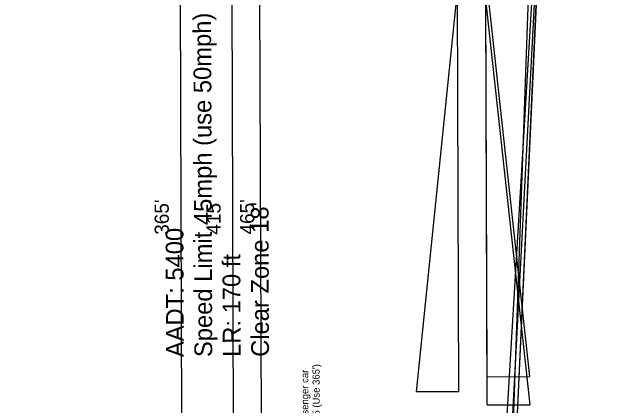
# Model space of a CAD drawing. Extents: x 17465868 to 18455672, y 7253752 to 7478845.
# Drawn here: x 18454911.4 to 18455165.1, y 7478499.2 to 7478665.7 of the extents above; entities that cross this region are included whole.
import ezdxf

# ---------------------------------------------------------------- set-up
doc = ezdxf.new("R2010")
doc.units = 0
for name, color, linetype in [('Clinton 225 CL Girders', 7, 'Continuous'), ('Clinton 225 CL Truss', 7, 'Continuous'), ('Clinton 225 Handrail', 7, 'Continuous'), ('Clinton 225 Metal Rail', 7, 'Continuous'), ('Clinton 225 MISC', 7, 'Continuous'), ('Dallas 126 CL Girder', 7, 'Continuous')]:
    doc.layers.add(name, color=color, linetype=linetype)

msp = doc.modelspace()

# ---------------------------------------------------------------- linework, layer by layer
at = {"layer": 'Clinton 225 CL Girders'}
for p, q in [((18455017.3, 7478353.71), (18455015.75, 7478818.71)), ((18455118.56, 7478354.05), (18455139.8, 7478819.14)), ((18455118.56, 7478354.05), (18455140.11, 7478819.12))]:
    msp.add_line(p, q, dxfattribs=at)
at = {"layer": 'Clinton 225 CL Truss'}
for p, q in [((18454981.97, 7478818.6), (18454983.19, 7478453.6)), ((18455118.23, 7478454.05), (18455140.11, 7478819.12))]:
    msp.add_line(p, q, dxfattribs=at)
at = {"layer": 'Clinton 225 Handrail'}
msp.add_line((18455118.56, 7478354.05), (18455135.01, 7478819.11), dxfattribs=at)
at = {"layer": 'Clinton 225 Metal Rail'}
for p, q in [((18455003.85, 7478818.67), (18455005.23, 7478403.67)), ((18455118.4, 7478404.05), (18455140.11, 7478819.12))]:
    msp.add_line(p, q, dxfattribs=at)
at = {"layer": 'Clinton 225 MISC'}
for p, q in [((18455111.72, 7478669.62), (18455130.29, 7478499.68)), ((18455112.29, 7478499.62), (18455111.72, 7478669.62)), ((18455112.29, 7478499.62), (18455130.29, 7478499.68))]:
    msp.add_line(p, q, dxfattribs=at)
at = {"layer": 'Dallas 126 CL Girder'}
for p, q in [((18455111.68, 7478681.52), (18455130.25, 7478511.59)), ((18455112.25, 7478511.53), (18455111.68, 7478681.52)), ((18455099.7, 7478675.19), (18455082.27, 7478505.13)), ((18455100.27, 7478505.19), (18455099.7, 7478675.19)), ((18455112.25, 7478511.53), (18455130.25, 7478511.59)), ((18455100.27, 7478505.19), (18455082.27, 7478505.13))]:
    msp.add_line(p, q, dxfattribs=at)
for radius in [15064.79, 15052.79, 15040.79, 15028.79]:
    msp.add_arc((18458471.78, 7463759.05), radius, 101.066879, 104.665109, dxfattribs=at)

# ---------------------------------------------------------------- texts
at = {"layer": 'Clinton 225 CL Girders'}
msp.add_text("465'", height=6, rotation=90.1905, dxfattribs=at).set_placement((18455013.85, 7478571.65))
at = {"layer": 'Clinton 225 CL Truss'}
for s, height, p in [("365'", 6, (18454977.75, 7478571.53)), ("L=1.47x35x7=360.15 (Use 365')", 3, (18455041.64, 7478459.69)), ('Design Vehicle: Passenger car', 3, (18455036.84, 7478459.67))]:
    msp.add_text(s, height=height, rotation=90.1905, dxfattribs=at).set_placement(p)
at = {"layer": 'Clinton 225 Metal Rail'}
msp.add_text("415'", height=6, rotation=90.1905, dxfattribs=at).set_placement((18454999.63, 7478571.6))
at = {"layer": 'Dallas 126 CL Girder'}
for s, p in [('Speed Limit 45mph (use 50mph)', (18454996.07, 7478519.87)), ("Clear Zone 18'", (18455020.07, 7478519.95)), ('AADT: 5400', (18454984.07, 7478519.83)), ('LR: 170 ft', (18455008.07, 7478519.91))]:
    msp.add_text(s, height=7.5, rotation=90.1905, dxfattribs=at).set_placement(p)

doc.saveas('drawing.dxf')
